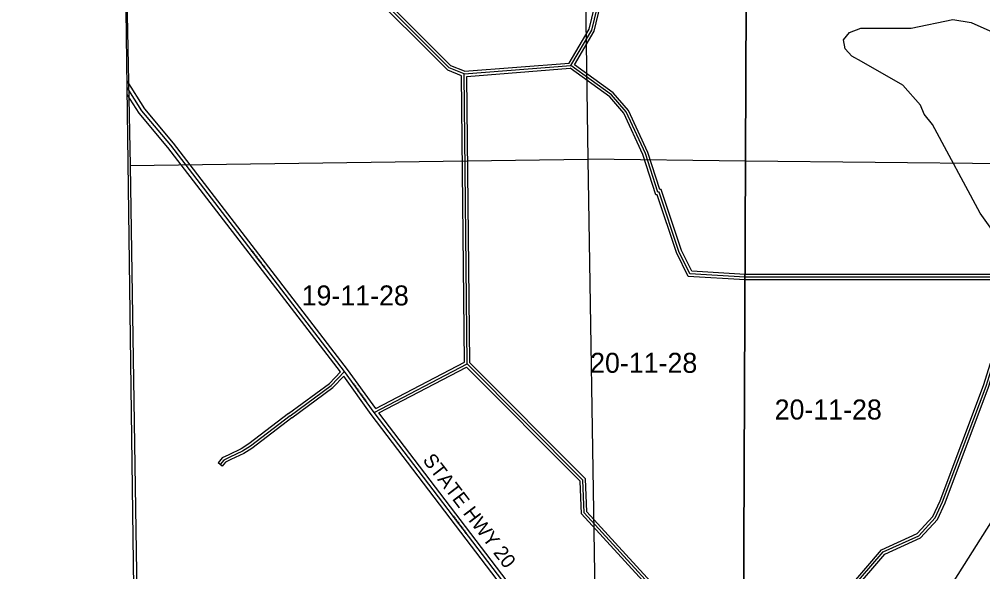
# Model space of a CAD drawing. Extents: x 457167 to 656239, y 1787309 to 1969297.
# Drawn here: x 489068 to 499897, y 1886987 to 1893199 of the extents above; entities that cross this region are included whole.
import ezdxf

# ---------------------------------------------------------------- set-up
doc = ezdxf.new("R2010")
doc.units = 0
for name, color, linetype in [('Level 1', 7, 'Continuous'), ('Level 10', 7, 'Continuous'), ('Level 2', 7, 'Continuous'), ('Level 22', 7, 'Continuous'), ('Level 23', 7, 'Continuous'), ('Level 28', 7, 'Continuous'), ('Level 31', 7, 'Continuous'), ('Level 32', 7, 'Continuous'), ('Level 34', 7, 'Continuous'), ('Level 5', 7, 'Continuous'), ('Level 63', 7, 'Continuous'), ('Level 7', 7, 'Continuous')]:
    doc.layers.add(name, color=color, linetype=linetype)

msp = doc.modelspace()

# ---------------------------------------------------------------- linework, layer by layer
at = {"layer": 'Level 1'}
for p, q in [((495383.161, 1896901.07), (495459.209, 1891625.008)), ((490210.541, 1896831.879), (490314.578, 1891555.671)), ((490314.578, 1891555.671), (495459.209, 1891625.008)), ((495459.209, 1891625.008), (495546.868, 1886270.773)), ((497232.566, 1891604.756), (495459.209, 1891625.008)), ((500415.738, 1891568.407), (497232.565, 1891604.756)), ((490314.578, 1891555.671), (490398.407, 1886235.506))]:
    msp.add_line(p, q, dxfattribs=at)
at = {"layer": 'Level 10'}
msp.add_lwpolyline([(490372.272, 1885683.713), (490281.141, 1892430.869), (490269.124, 1893301.89), (490244.122, 1893368.891), (490203.086, 1895244.934), (490183.066, 1896244.957), (490193.061, 1896486.963), (490145.052, 1896928.972), (490134.029, 1898121.001), (490096.013, 1898888.018), (490076.986, 1900289.05), (490053.98, 1900622.057), (490081.969, 1901172.071), (490074.961, 1901556.08), (490044.888, 1905351.168), (490043.886, 1905424.169), (490022.847, 1907445.216)], dxfattribs=at)
at = {"layer": 'Level 22'}
for p, q in [((493056.516, 1888778.463), (492725.228, 1889238.486)), ((494978.352, 1886259.776), (493056.516, 1888778.463))]:
    msp.add_line(p, q, dxfattribs=at)
msp.add_lwpolyline([(492725.228, 1889238.486), (490770.102, 1891782.176), (490446.803, 1892167.273), (490281.022, 1892430.936)], dxfattribs=at)
at = {"layer": 'Level 23'}
for p, q in [((493074.63, 1888821.76), (492757.324, 1889262.368)), ((493024.381, 1888754.637), (492714.926, 1889184.343)), ((494904.426, 1886290.72), (493024.381, 1888754.637)), ((495005.522, 1886290.109), (493110.967, 1888773.042))]:
    msp.add_line(p, q, dxfattribs=at)
for points in [[(492757.324, 1889262.367), (490801.292, 1891807.236), (490479.204, 1892190.891), (490280.082, 1892507.579)], [(492678.749, 1889233.319), (490738.912, 1891757.116), (490414.402, 1892143.656), (490282.18, 1892353.947)]]:
    msp.add_lwpolyline(points, dxfattribs=at)
at = {"layer": 'Level 31'}
for p, q in [((494067.033, 1892583.271), (495267.947, 1892677.676)), ((494101.137, 1889323.719), (494067.033, 1892583.271)), ((493056.516, 1888778.463), (494101.137, 1889323.719))]:
    msp.add_line(p, q, dxfattribs=at)
for points in [[(495267.947, 1892677.676), (495503.096, 1893076.671), (495622.286, 1893576.174), (495765.339, 1893858.838), (495816.267, 1894017.17), (496293.538, 1894448.215), (496677.644, 1894588.019), (496853.041, 1894703.996), (497071.088, 1894977.978), (497248.4, 1895319.049), (497248.487, 1895319.111)], [(494067.033, 1892583.271), (493900.372, 1892650.913), (491975.691, 1894577.294), (491759.767, 1894720.076), (490203.295, 1895244.496)], [(497226.975, 1890300.4), (497226.903, 1890300.4), (496606.894, 1890336.884), (496483.304, 1890587.607), (496261.334, 1891255.5), (496244.797, 1891255.571), (496105.148, 1891689.646), (495890.596, 1892157.501), (495724.789, 1892350.226), (495267.947, 1892677.676)], [(499446.294, 1887774.127), (499934.886, 1889072.839), (500010.642, 1889314.346), (500194.886, 1889488.851), (500212.544, 1889755.331), (500246.145, 1889880.285), (500246.811, 1890038.834), (500197.65, 1890222.32), (500139.447, 1890297.476), (497226.974, 1890300.4)], [(496670.867, 1886276.819), (495418.535, 1887649.916), (495403.904, 1888016.903), (494101.137, 1889323.719)], [(492114.295, 1888741.166), (492574.417, 1889080.964), (492725.228, 1889238.486)], [(492114.295, 1888741.166), (491665.92, 1888398.776), (491578.207, 1888342.801), (491435.101, 1888275.07), (491367.849, 1888242.64), (491326.917, 1888193.002)], [(498173.89, 1886311.839), (498216.407, 1886511.666), (498409.014, 1886777.764), (498777.575, 1887210.031), (499178.146, 1887391.976), (499362.508, 1887591.202), (499446.294, 1887774.127)]]:
    msp.add_lwpolyline(points, dxfattribs=at)
at = {"layer": 'Level 32'}
for p, q in [((494071.749, 1892613.735), (495250.031, 1892706.359)), ((494097.326, 1892555.559), (495259.376, 1892646.907)), ((494070.946, 1889341.801), (494037.244, 1892562.984)), ((494131.009, 1889336.247), (494097.326, 1892555.558)), ((493074.63, 1888821.758), (494070.946, 1889341.801)), ((493110.967, 1888773.042), (494095.466, 1889286.916)), ((491350.063, 1888173.916), (491303.772, 1888212.089))]:
    msp.add_line(p, q, dxfattribs=at)
for points in [[(495250.03, 1892706.361), (495474.961, 1893088.019), (495593.924, 1893586.571), (495737.503, 1893870.276), (495790.176, 1894034.031), (496277.776, 1894474.404), (496664.053, 1894614.998), (496832.527, 1894726.398), (497045.808, 1894994.391), (497225.154, 1895339.372), (497248.646, 1895355.911)], [(494071.749, 1892613.735), (493917.293, 1892676.423), (491994.769, 1894600.645), (491773.052, 1894747.258), (490232.861, 1895266.191)], [(494037.245, 1892562.984), (493883.451, 1892625.403), (491956.613, 1894553.943), (491746.483, 1894692.895), (490234.221, 1895202.418)], [(495307.724, 1892686.076), (495531.231, 1893065.323), (495650.646, 1893565.776), (495793.175, 1893847.401), (495842.358, 1894000.309), (496309.3, 1894422.026), (496691.235, 1894561.039), (496873.553, 1894681.594), (497096.368, 1894961.566), (497248.207, 1895253.637)], [(497227.104, 1890330.441), (496626.084, 1890365.807), (496511.124, 1890599.024), (496283.008, 1891285.409), (496266.691, 1891285.478), (496133.161, 1891700.531), (495916.101, 1892173.856), (495745.187, 1892372.516), (495307.723, 1892686.076)], [(497226.846, 1890270.399), (497226.006, 1890270.4), (496587.705, 1890307.961), (496455.485, 1890576.191), (496239.66, 1891225.591), (496222.904, 1891225.663), (496077.136, 1891678.761), (495865.092, 1892141.146), (495704.391, 1892327.936), (495259.377, 1892646.908)], [(499474.005, 1887762.584), (499963.26, 1889063.06), (500036.934, 1889297.926), (500224.045, 1889475.146), (500242.283, 1889750.396), (500276.129, 1889876.26), (500276.828, 1890042.721), (500225.066, 1890235.916), (500154.17, 1890327.462), (497227.799, 1890330.399), (497227.103, 1890330.441)], [(499418.583, 1887785.669), (499906.512, 1889082.618), (499984.35, 1889330.766), (500165.728, 1889502.555), (500182.805, 1889760.266), (500216.16, 1889884.311), (500216.794, 1890034.946), (500170.234, 1890208.724), (500124.725, 1890267.491), (497226.845, 1890270.399)], [(496683.982, 1886306.958), (495448.076, 1887662.047), (495433.414, 1888029.794), (494131.009, 1889336.248)], [(492096.087, 1888765.01), (492554.526, 1889103.569), (492678.749, 1889233.319)], [(496603.468, 1886306.199), (495388.994, 1887637.786), (495374.393, 1888004.013), (494095.466, 1889286.915)], [(492132.502, 1888717.321), (492594.309, 1889058.358), (492714.926, 1889184.343)], [(492096.087, 1888765.01), (491648.716, 1888423.387), (491563.664, 1888369.107), (491422.17, 1888302.14), (491348.89, 1888266.804), (491303.772, 1888212.089)], [(492132.502, 1888717.321), (491683.123, 1888374.166), (491592.751, 1888316.493), (491448.034, 1888247.999), (491386.808, 1888218.475), (491350.063, 1888173.916)], [(498149.446, 1886341.109), (498188.384, 1886524.116), (498385.41, 1886796.321), (498759.082, 1887234.582), (499160.235, 1887416.79), (499337.23, 1887608.057), (499418.584, 1887785.67)], [(498210.9, 1886341.623), (498244.43, 1886499.215), (498432.617, 1886759.207), (498796.067, 1887185.48), (499196.059, 1887367.161), (499387.785, 1887574.347), (499474.005, 1887762.583)]]:
    msp.add_lwpolyline(points, dxfattribs=at)
at = {"layer": 'Level 5'}
msp.add_lwpolyline([(498180.249, 1884039.649), (498741.522, 1884888.156), (498909.289, 1885212.726), (498993.505, 1885479.222), (499120.735, 1886162.41), (500444.589, 1888258.926)], dxfattribs=at)
at = {"layer": 'Level 63'}
for points in [[(457410.247, 1878726.517), (497176.541, 1878534.741), (497371.387, 1923990.389), (457653.971, 1924182.684), (457410.247, 1878726.517)], [(497176.54, 1878534.741), (536942.563, 1878385.707), (537088.612, 1923840.983), (497371.386, 1923990.389), (497176.54, 1878534.741)]]:
    msp.add_lwpolyline(points, dxfattribs=at)
at = {"layer": 'Level 7'}
msp.add_lwpolyline([(500393.415, 1890493.267), (500110.567, 1890677.548), (499869.896, 1891020.123), (499331.228, 1892013.879), (499239.884, 1892130.881), (499198.531, 1892231.052), (498999.183, 1892456.786), (498533.19, 1892725.056), (498425.016, 1892783.736), (498350.254, 1892867.356), (498333.901, 1892967.429), (498400.861, 1893050.591), (498526.062, 1893100.224), (499092.933, 1893098.391), (499560.09, 1893196.92), (499768.404, 1893162.921), (500009.8, 1893053.762), (500325.602, 1892744.309)], dxfattribs=at)

# ---------------------------------------------------------------- texts
at = {"layer": 'Level 2'}
for s, p in [('19-11-28', (492242.145, 1889980.829)), ('20-11-28', (495484.407, 1889223.407)), ('20-11-28', (497558.52, 1888698.445))]:
    msp.add_text(s, height=225, dxfattribs=at).set_placement(p)
at = {"layer": 'Level 28'}
msp.add_text('STATE HWY 20', height=160, rotation=307.3440611, dxfattribs=at).set_placement((493595.877, 1888240.251))
at = {"layer": 'Level 34'}
for rotation, p in [(307.545825, (491665.202, 1890597.109)), (305.7589917, (492811.155, 1889097.781)), (307.3440611, (493935.277, 1887606.187))]:
    msp.add_text('STATE HWY 20', height=25, rotation=rotation, dxfattribs=at).set_placement(p)

doc.saveas('drawing.dxf')
